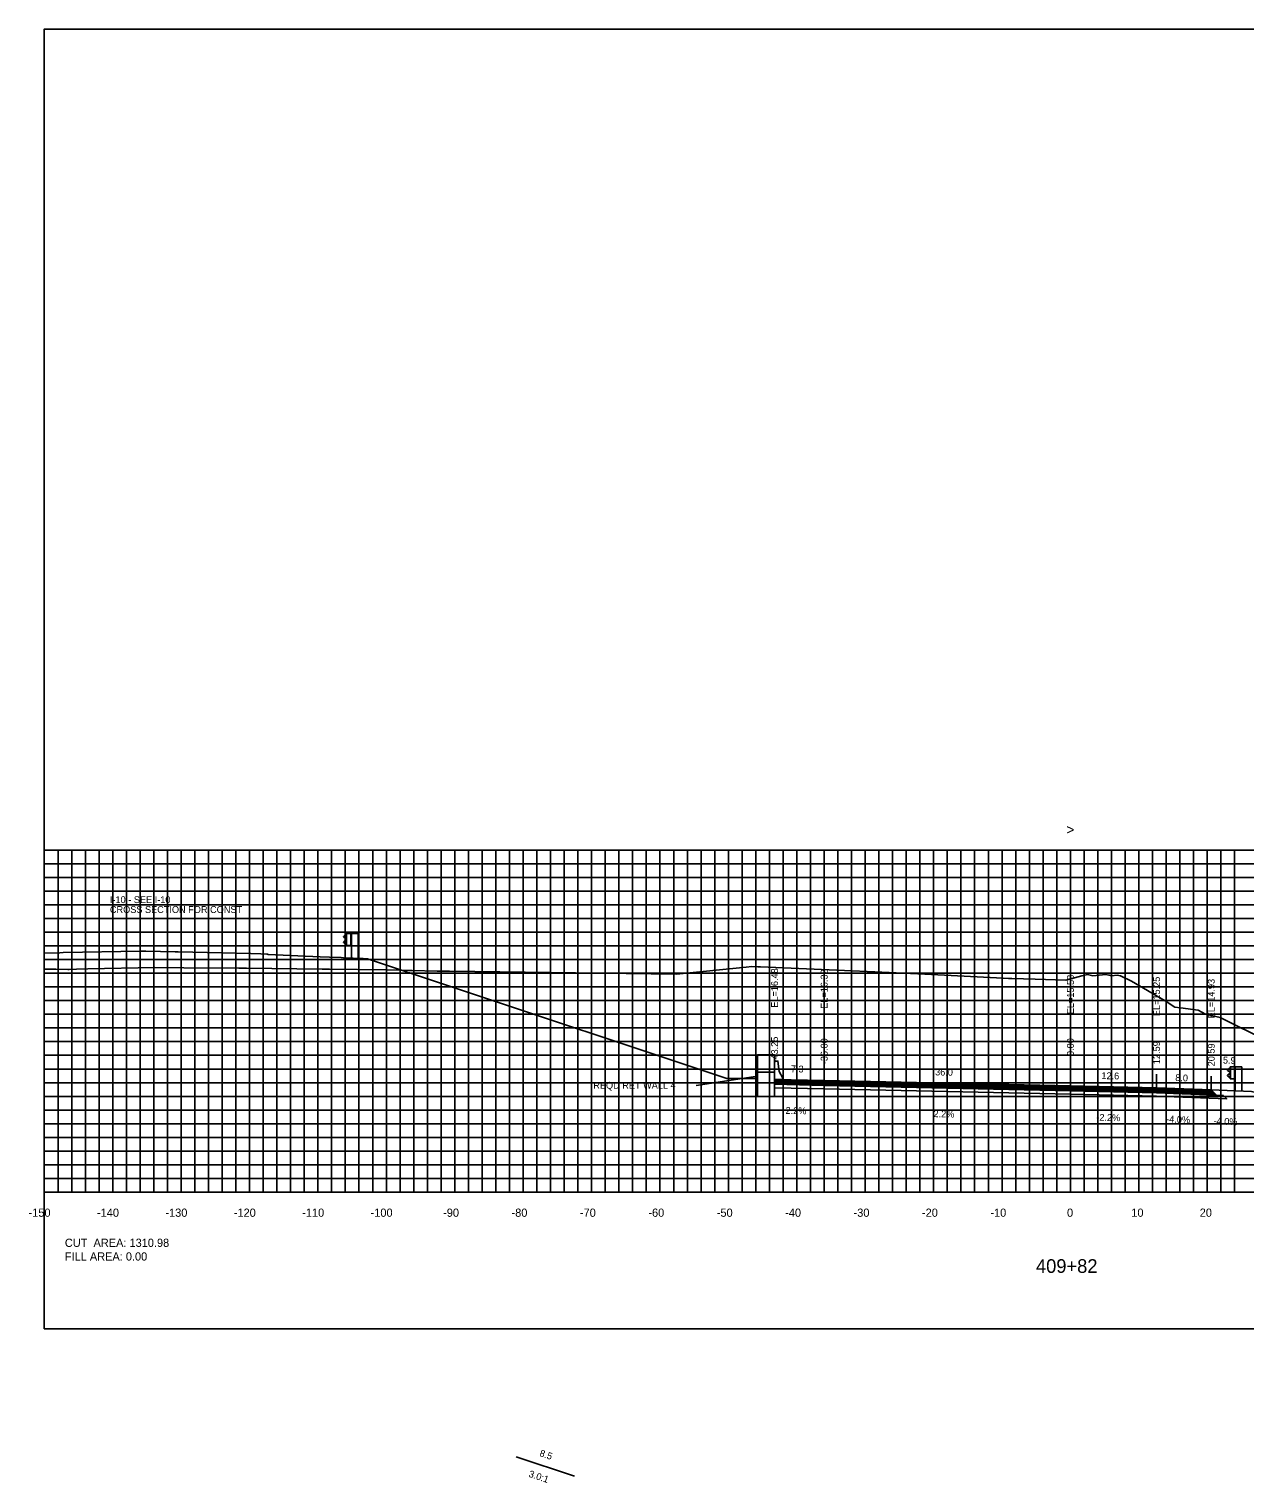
# Model space of a CAD drawing. Extents: x 1800976 to 1805104, y 250057 to 250580.
# Drawn here: x 1803838.8 to 1804016.5, y 250056.9 to 250269.4 of the extents above; entities that cross this region are included whole.
import ezdxf

# ---------------------------------------------------------------- set-up
doc = ezdxf.new("R2010")
doc.units = 0
for name, color, linetype in [('1', 7, 'Continuous'), ('10', 7, 'Continuous'), ('3', 7, 'Continuous'), ('4', 7, 'Continuous'), ('60', 7, 'Continuous'), ('ANNO-TXT', 7, 'Continuous'), ('BASE', 7, 'Continuous'), ('CL-CNST', 7, 'Continuous'), ('Default', 7, 'Continuous'), ('Level 1', 7, 'Continuous'), ('Level 62', 7, 'Continuous'), ('LOWER BINDER', 7, 'Continuous'), ('M-ROADS', 7, 'Continuous'), ('UPPER BINDER', 7, 'Continuous'), ('WEARING', 7, 'Continuous')]:
    doc.layers.add(name, color=color, linetype=linetype)

msp = doc.modelspace()

# ---------------------------------------------------------------- linework, layer by layer
for p, q in [((1803947.75, 250115.92), (1803947.75, 250117.92)), ((1803955, 250115.76), (1803955, 250117.76)), ((1803991, 250114.96), (1803991, 250116.96)), ((1804003.59, 250114.69), (1804003.59, 250116.69)), ((1804011.59, 250114.37), (1804011.59, 250116.37))]:
    msp.add_line(p, q)
msp.add_lwpolyline([(1803841, 250079.43), (1804141, 250079.43), (1804141, 250269.43), (1803841, 250269.43)], close=True)
at = {"layer": '3'}
msp.add_line((1803936.29, 250115.01), (1803945.25, 250116.39), dxfattribs=at)
at = {"layer": '60'}
for p, q in [((1803840.94, 250149.43), (1803841, 250149.43)), ((1803841, 250099.43), (1803841, 250149.43)), ((1803840.94, 250139.43), (1803841, 250139.43)), ((1803840.94, 250129.43), (1803841, 250129.43)), ((1803840.94, 250119.43), (1803841, 250119.43)), ((1803840.94, 250109.43), (1803841, 250109.43)), ((1803840.94, 250099.43), (1803841, 250099.43)), ((1803841, 250099.43), (1804141, 250099.43)), ((1803841, 250099.37), (1803841, 250099.43)), ((1803851, 250099.37), (1803851, 250099.43)), ((1803861, 250099.37), (1803861, 250099.43)), ((1803871, 250099.37), (1803871, 250099.43)), ((1803881, 250099.37), (1803881, 250099.43)), ((1803891, 250099.37), (1803891, 250099.43)), ((1803901, 250099.37), (1803901, 250099.43)), ((1803911, 250099.37), (1803911, 250099.43)), ((1803921, 250099.37), (1803921, 250099.43)), ((1803931, 250099.37), (1803931, 250099.43)), ((1803941, 250099.37), (1803941, 250099.43)), ((1803951, 250099.37), (1803951, 250099.43)), ((1803961, 250099.37), (1803961, 250099.43)), ((1803971, 250099.37), (1803971, 250099.43)), ((1803981, 250099.37), (1803981, 250099.43)), ((1803991, 250099.37), (1803991, 250099.43)), ((1804001, 250099.37), (1804001, 250099.43)), ((1804011, 250099.37), (1804011, 250099.43))]:
    msp.add_line(p, q, dxfattribs=at)
at = {"layer": 'BASE'}
msp.add_lwpolyline([(1803947.75, 250115.2), (1803955, 250115.04), (1803991, 250114.24), (1804003.59, 250113.97), (1804012.34, 250113.62), (1804013.34, 250113.58), (1804013.86, 250113.06), (1804003.59, 250113.47), (1803991, 250113.74), (1803955, 250114.54), (1803947.75, 250114.7)], close=True, dxfattribs=at)
at = {"layer": 'CL-CNST'}
for p, q in [((1803940.75, 250116.04), (1803945.25, 250116.04)), ((1803909.98, 250060.76), (1803918.48, 250057.92))]:
    msp.add_line(p, q, dxfattribs=at)
for points in [[(1803841, 250134.34), (1803843.28, 250134.43), (1803843.77, 250134.45), (1803854.99, 250134.66), (1803855.82, 250134.67), (1803860.13, 250134.57), (1803860.57, 250134.56), (1803871.17, 250134.31), (1803872.64, 250134.27), (1803873.51, 250134.24), (1803873.64, 250134.23), (1803873.71, 250134.17), (1803873.72, 250134.16), (1803881.31, 250133.84), (1803882.7, 250133.78), (1803884.38, 250133.71), (1803884.71, 250133.7), (1803887.62, 250133.58), (1803888.24, 250133.55), (1803898.9, 250129.99), (1803940.75, 250116.04), (1803942.32, 250116.04), (1803945.24, 250116.04)], [(1803947.75, 250115.92), (1803955, 250115.76), (1803991, 250114.96), (1804003.59, 250114.69), (1804011.59, 250114.37), (1804017.45, 250114.13), (1804041.45, 250108.13), (1804045.45, 250108.13), (1804054.74, 250110.45)]]:
    msp.add_lwpolyline(points, dxfattribs=at)
for points in [[(1803947.75, 250116.99), (1803945.25, 250116.99), (1803945.25, 250119.49), (1803947.75, 250119.49)], [(1803945.25, 250113.43), (1803947.75, 250113.43), (1803947.75, 250116.99), (1803945.25, 250116.99)]]:
    msp.add_lwpolyline(points, close=True, dxfattribs=at)
at = {"layer": 'Default'}
msp.add_line((1803947.75, 250115.92), (1803947.75, 250118.59), dxfattribs=at)
msp.add_lwpolyline([(1803947.75, 250118.59), (1803948.25, 250118.59), (1803948.43, 250117.09), (1803948.98, 250116.09), (1803949, 250115.92), (1803947.75, 250115.92)], dxfattribs=at)
at = {"layer": 'Level 1'}
for p, q in [((1803885.13, 250137.09), (1803884.77, 250136.79)), ((1803884.77, 250136.72), (1803885.13, 250136.44)), ((1803885.13, 250136.3), (1803884.77, 250136)), ((1803885.13, 250137.24), (1803885.13, 250135.49)), ((1803886.88, 250137.24), (1803885.13, 250137.24)), ((1803885.18, 250137.24), (1803885.18, 250135.49)), ((1803885.83, 250137.24), (1803885.83, 250135.49)), ((1803885.88, 250137.24), (1803885.88, 250133.72)), ((1803886.88, 250137.24), (1803886.88, 250133.68)), ((1803884.77, 250135.93), (1803885.13, 250135.64)), ((1803885.88, 250135.49), (1803885.13, 250135.49)), ((1804014.33, 250117.6), (1804013.97, 250117.3)), ((1804013.97, 250117.23), (1804014.33, 250116.95)), ((1804014.33, 250117.75), (1804014.33, 250116)), ((1804016.08, 250117.75), (1804014.33, 250117.75)), ((1804014.38, 250117.75), (1804014.38, 250116)), ((1804015.03, 250117.75), (1804015.03, 250116)), ((1804015.08, 250117.75), (1804015.08, 250114.23)), ((1804016.08, 250117.75), (1804016.08, 250114.19)), ((1804014.33, 250116.81), (1804013.97, 250116.51)), ((1804013.97, 250116.44), (1804014.33, 250116.15)), ((1804015.08, 250116), (1804014.33, 250116))]:
    msp.add_line(p, q, dxfattribs=at)
for centre in [(1803884.8, 250136.76), (1803884.8, 250135.96), (1804014, 250117.27), (1804014, 250116.47)]:
    msp.add_arc(centre, 0.05, 135, 226.6208, dxfattribs=at)
at = {"layer": 'Level 62'}
for p, q in [((1803841, 250149.43), (1804141, 250149.43)), ((1803841, 250099.43), (1803841, 250149.43)), ((1803843, 250099.43), (1803843, 250149.43)), ((1803845, 250099.43), (1803845, 250149.43)), ((1803847, 250099.43), (1803847, 250149.43)), ((1803849, 250099.43), (1803849, 250149.43)), ((1803851, 250099.43), (1803851, 250149.43)), ((1803853, 250099.43), (1803853, 250149.43)), ((1803855, 250099.43), (1803855, 250149.43)), ((1803857, 250099.43), (1803857, 250149.43)), ((1803859, 250099.43), (1803859, 250149.43)), ((1803861, 250099.43), (1803861, 250149.43)), ((1803863, 250099.43), (1803863, 250149.43)), ((1803865, 250099.43), (1803865, 250149.43)), ((1803867, 250099.43), (1803867, 250149.43)), ((1803869, 250099.43), (1803869, 250149.43)), ((1803871, 250099.43), (1803871, 250149.43)), ((1803873, 250099.43), (1803873, 250149.43)), ((1803875, 250099.43), (1803875, 250149.43)), ((1803877, 250099.43), (1803877, 250149.43)), ((1803879, 250099.43), (1803879, 250149.43)), ((1803881, 250099.43), (1803881, 250149.43)), ((1803883, 250099.43), (1803883, 250149.43)), ((1803885, 250099.43), (1803885, 250149.43)), ((1803887, 250099.43), (1803887, 250149.43)), ((1803889, 250099.43), (1803889, 250149.43)), ((1803891, 250099.43), (1803891, 250149.43)), ((1803893, 250099.43), (1803893, 250149.43)), ((1803895, 250099.43), (1803895, 250149.43)), ((1803897, 250099.43), (1803897, 250149.43)), ((1803899, 250099.43), (1803899, 250149.43)), ((1803901, 250099.43), (1803901, 250149.43)), ((1803903, 250099.43), (1803903, 250149.43)), ((1803905, 250099.43), (1803905, 250149.43)), ((1803907, 250099.43), (1803907, 250149.43)), ((1803909, 250099.43), (1803909, 250149.43)), ((1803911, 250099.43), (1803911, 250149.43)), ((1803913, 250099.43), (1803913, 250149.43)), ((1803915, 250099.43), (1803915, 250149.43)), ((1803917, 250099.43), (1803917, 250149.43)), ((1803919, 250099.43), (1803919, 250149.43)), ((1803921, 250099.43), (1803921, 250149.43)), ((1803923, 250099.43), (1803923, 250149.43)), ((1803925, 250099.43), (1803925, 250149.43)), ((1803927, 250099.43), (1803927, 250149.43)), ((1803929, 250099.43), (1803929, 250149.43)), ((1803931, 250099.43), (1803931, 250149.43)), ((1803933, 250099.43), (1803933, 250149.43)), ((1803935, 250099.43), (1803935, 250149.43)), ((1803937, 250099.43), (1803937, 250149.43)), ((1803939, 250099.43), (1803939, 250149.43)), ((1803941, 250099.43), (1803941, 250149.43)), ((1803943, 250099.43), (1803943, 250149.43)), ((1803945, 250099.43), (1803945, 250149.43)), ((1803947, 250099.43), (1803947, 250149.43)), ((1803949, 250099.43), (1803949, 250149.43)), ((1803951, 250099.43), (1803951, 250149.43)), ((1803953, 250099.43), (1803953, 250149.43)), ((1803955, 250099.43), (1803955, 250149.43)), ((1803957, 250099.43), (1803957, 250149.43)), ((1803959, 250099.43), (1803959, 250149.43)), ((1803961, 250099.43), (1803961, 250149.43)), ((1803963, 250099.43), (1803963, 250149.43)), ((1803965, 250099.43), (1803965, 250149.43)), ((1803967, 250099.43), (1803967, 250149.43)), ((1803969, 250099.43), (1803969, 250149.43)), ((1803971, 250099.43), (1803971, 250149.43)), ((1803973, 250099.43), (1803973, 250149.43)), ((1803975, 250099.43), (1803975, 250149.43)), ((1803977, 250099.43), (1803977, 250149.43)), ((1803979, 250099.43), (1803979, 250149.43)), ((1803981, 250099.43), (1803981, 250149.43)), ((1803983, 250099.43), (1803983, 250149.43)), ((1803985, 250099.43), (1803985, 250149.43)), ((1803987, 250099.43), (1803987, 250149.43)), ((1803989, 250099.43), (1803989, 250149.43)), ((1803991, 250099.43), (1803991, 250149.43)), ((1803993, 250099.43), (1803993, 250149.43)), ((1803995, 250099.43), (1803995, 250149.43)), ((1803997, 250099.43), (1803997, 250149.43)), ((1803999, 250099.43), (1803999, 250149.43)), ((1804001, 250099.43), (1804001, 250149.43)), ((1804003, 250099.43), (1804003, 250149.43)), ((1804005, 250099.43), (1804005, 250149.43)), ((1804007, 250099.43), (1804007, 250149.43)), ((1804009, 250099.43), (1804009, 250149.43)), ((1804011, 250099.43), (1804011, 250149.43)), ((1804013, 250099.43), (1804013, 250149.43)), ((1804015, 250099.43), (1804015, 250149.43)), ((1803841, 250147.43), (1804141, 250147.43)), ((1803841, 250145.43), (1804141, 250145.43)), ((1803841, 250143.43), (1804141, 250143.43)), ((1803841, 250141.43), (1804141, 250141.43)), ((1803841, 250139.43), (1804141, 250139.43)), ((1803841, 250137.43), (1804141, 250137.43)), ((1803841, 250135.43), (1804141, 250135.43)), ((1803841, 250133.43), (1804141, 250133.43)), ((1803841, 250131.43), (1804141, 250131.43)), ((1803841, 250129.43), (1804141, 250129.43)), ((1803841, 250127.43), (1804141, 250127.43)), ((1803841, 250125.43), (1804141, 250125.43)), ((1803841, 250123.43), (1804141, 250123.43)), ((1803841, 250121.43), (1804141, 250121.43)), ((1803841, 250119.43), (1804141, 250119.43)), ((1803841, 250117.43), (1804141, 250117.43)), ((1803841, 250115.43), (1804141, 250115.43)), ((1803841, 250113.43), (1804141, 250113.43)), ((1803841, 250111.43), (1804141, 250111.43)), ((1803841, 250109.43), (1804141, 250109.43)), ((1803841, 250107.43), (1804141, 250107.43)), ((1803841, 250105.43), (1804141, 250105.43)), ((1803841, 250103.43), (1804141, 250103.43)), ((1803841, 250101.43), (1804141, 250101.43)), ((1803841, 250099.43), (1804141, 250099.43))]:
    msp.add_line(p, q, dxfattribs=at)
at = {"layer": 'LOWER BINDER'}
for points in [[(1803955, 250115.42), (1803991, 250114.62), (1804003.59, 250114.35), (1804011.95, 250114.01), (1804012.14, 250113.81), (1804003.59, 250114.16), (1803991, 250114.43), (1803955, 250115.23), (1803947.75, 250115.39), (1803947.75, 250115.58)], [(1803955, 250115.23), (1803991, 250114.43), (1804003.59, 250114.16), (1804012.14, 250113.81), (1804012.34, 250113.62), (1804003.59, 250113.97), (1803991, 250114.24), (1803955, 250115.04), (1803947.75, 250115.2), (1803947.75, 250115.39)]]:
    msp.add_lwpolyline(points, close=True, dxfattribs=at)
at = {"layer": 'M-ROADS'}
msp.add_lwpolyline([(1803841, 250132.04), (1803842.66, 250132.01), (1803844.45, 250131.96), (1803844.61, 250131.97), (1803845.7, 250132.03), (1803847.34, 250132.06), (1803857.17, 250132.25), (1803861.38, 250132.22), (1803869.41, 250132.17), (1803870.54, 250132.15), (1803881.62, 250132.04), (1803882.67, 250132.03), (1803890.9, 250131.91), (1803892.92, 250131.88), (1803893.18, 250131.88), (1803894.34, 250131.85), (1803894.43, 250131.85), (1803894.78, 250131.84), (1803898.41, 250131.75), (1803900.22, 250131.73), (1803933.41, 250131.28), (1803943.58, 250132.33), (1803944.42, 250132.41), (1803945.32, 250132.36), (1803945.69, 250132.35), (1803950.16, 250132.16), (1803957.98, 250131.81), (1803962.42, 250131.62), (1803969.71, 250131.31), (1803972.61, 250131.16), (1803981.19, 250130.72), (1803981.93, 250130.68), (1803982.44, 250130.66), (1803985.84, 250130.54), (1803990.32, 250130.4), (1803992.66, 250131.04), (1803993.49, 250131.22), (1803994.28, 250131.05), (1803994.76, 250131.1), (1803996.14, 250131.26), (1803996.65, 250131.14), (1803996.98, 250131.06), (1803997.83, 250131.16), (1803998.3, 250131.06), (1803999.95, 250130.25), (1804004.87, 250127.41), (1804006.24, 250126.49), (1804007.1, 250126.38), (1804009.65, 250126.05), (1804010.74, 250125.47), (1804012.9, 250124.98), (1804019.87, 250121.52)], dxfattribs=at)
at = {"layer": 'UPPER BINDER'}
msp.add_lwpolyline([(1804003.59, 250114.35), (1804011.95, 250114.01), (1804011.75, 250114.21), (1804003.59, 250114.54), (1803991, 250114.81), (1803955, 250115.61), (1803947.75, 250115.77), (1803947.75, 250115.58), (1803955, 250115.42), (1803991, 250114.62)], close=True, dxfattribs=at)
at = {"layer": 'WEARING'}
msp.add_lwpolyline([(1804003.59, 250114.54), (1804011.75, 250114.21), (1804011.59, 250114.37), (1804003.59, 250114.69), (1803991, 250114.96), (1803955, 250115.76), (1803947.75, 250115.92), (1803947.75, 250115.77), (1803955, 250115.61), (1803991, 250114.81)], close=True, dxfattribs=at)

# ---------------------------------------------------------------- texts
msp.add_text('3.0:1', height=1, rotation=341.5652).set_placement((1803911.73, 250057.85))
at = {"layer": '1'}
msp.add_text('409+82', height=2, dxfattribs=at).set_placement((1803985.96, 250087.63))
at = {"layer": '10'}
for s, p in [('-150', (1803838.7, 250095.83)), ('-140', (1803848.7, 250095.83)), ('-130', (1803858.7, 250095.83)), ('-120', (1803868.7, 250095.83)), ('-110', (1803878.7, 250095.83)), ('-100', (1803888.7, 250095.83)), ('-90', (1803899.3, 250095.83)), ('-80', (1803909.3, 250095.83)), ('-70', (1803919.3, 250095.83)), ('-60', (1803929.3, 250095.83)), ('-50', (1803939.3, 250095.83)), ('-40', (1803949.3, 250095.83)), ('-30', (1803959.3, 250095.83)), ('-20', (1803969.3, 250095.83)), ('-10', (1803979.3, 250095.83)), ('0', (1803990.5, 250095.83)), ('10', (1803999.9, 250095.83)), ('20', (1804009.9, 250095.83))]:
    msp.add_text(s, height=1.2, dxfattribs=at).set_placement(p)
at = {"layer": '3'}
for s, p in [('I-10 - SEE I-10 ', (1803850.59, 250141.68)), ('CROSS SECTION FOR CONST ', (1803850.59, 250140.24)), ('REQD RET WALL 4', (1803921.25, 250114.55))]:
    msp.add_text(s, height=1, dxfattribs=at).set_placement(p)
for s, p in [('EL=16.48', (1803948.25, 250126.39)), ('EL=16.32', (1803955.5, 250126.23)), ('EL=15.53', (1803991.5, 250125.44)), ('EL=15.25', (1804004.09, 250125.16)), ('EL=14.93', (1804012.09, 250124.84)), ('-43.25', (1803948.25, 250118.37)), ('-36.00', (1803955.5, 250118.13)), ('0.00', (1803991.5, 250119.33)), ('12.59', (1804004.09, 250118.14)), ('20.59', (1804012.09, 250117.82))]:
    msp.add_text(s, height=1, rotation=90, dxfattribs=at).set_placement(p)
at = {"layer": '4'}
for s, rotation, p in [('5.9', 357.7094, (1804013.28, 250118.24)), ('7.3', 358.7397, (1803950.12, 250116.96)), ('36.0', 358.7397, (1803971.21, 250116.5)), ('12.6', 358.7397, (1803995.52, 250115.96)), ('8.0', 357.7094, (1804006.31, 250115.68)), ('2.2%', 358.7397, (1803949.35, 250110.88)), ('2.2%', 358.7397, (1803970.98, 250110.4)), ('-2.2%', 358.7397, (1803994.78, 250109.88)), ('-4.0%', 357.7094, (1804004.98, 250109.63)), ('-4.0%', 357.7094, (1804011.91, 250109.35)), ('8.5', 341.5652, (1803913.31, 250060.88))]:
    msp.add_text(s, height=1, rotation=rotation, dxfattribs=at).set_placement(p)
at = {"layer": '60'}
for s, height, p in [('>', 1.5, (1803990.39, 250151.68)), ('-', 0.0001, (1803841, 250099.43))]:
    msp.add_text(s, height=height, dxfattribs=at).set_placement(p)
at = {"layer": 'ANNO-TXT'}
for s, p in [('CUT  AREA: 1310.98', (1803844, 250091.43)), ('FILL AREA: 0.00', (1803844, 250089.43))]:
    msp.add_text(s, height=1.2, dxfattribs=at).set_placement(p)

doc.saveas('drawing.dxf')
